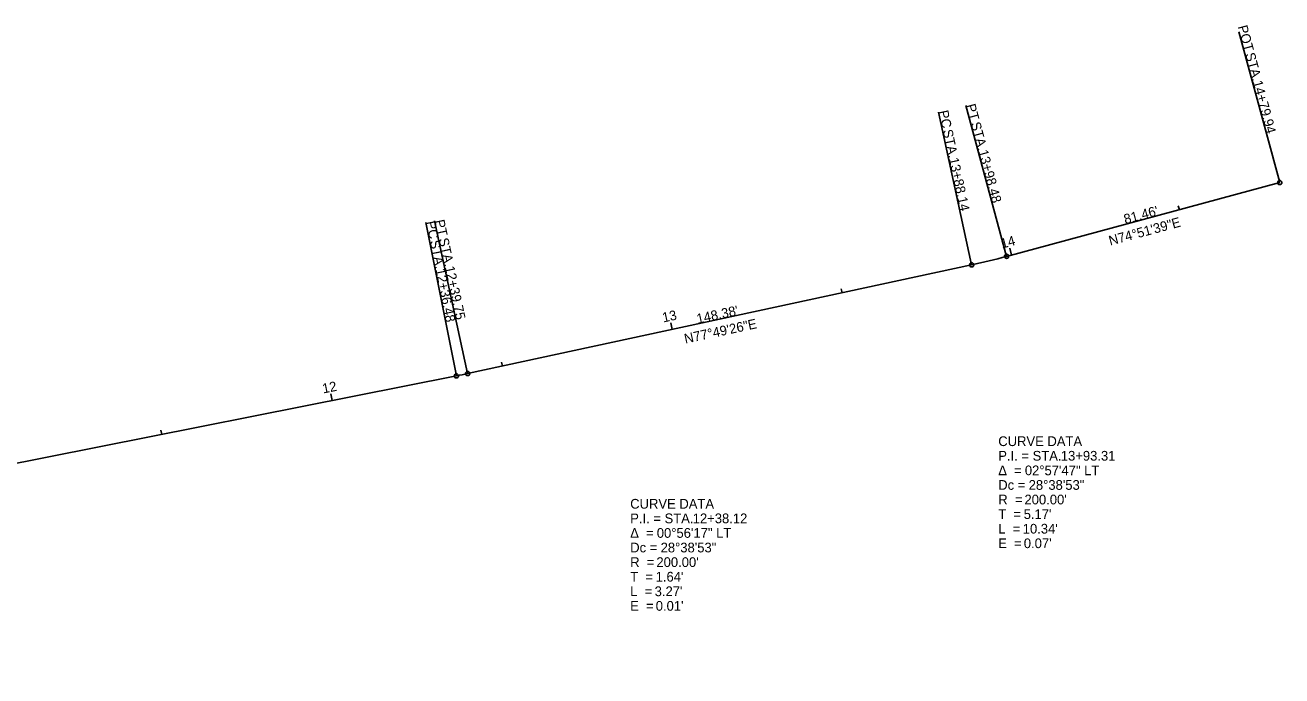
# Model space of a CAD drawing. Extents: x 1749457 to 1750917, y -159140 to -158804.
# Drawn here: x 1750555.2 to 1750916.8, y -158991.8 to -158804.4 of the extents above; entities that cross this region are included whole.
import ezdxf

# ---------------------------------------------------------------- set-up
doc = ezdxf.new("R2010")
doc.units = 0
for name, color, linetype in [('ALIGN', 7, 'Continuous'), ('C-STM STR', 7, 'Continuous'), ('SRF', 7, 'Continuous'), ('SRF-CONT EG MAJ', 7, 'Continuous'), ('SRF-CONT EG MIN', 7, 'Continuous'), ('TEXT', 7, 'Continuous')]:
    doc.layers.add(name, color=color, linetype=linetype)

msp = doc.modelspace()

# ---------------------------------------------------------------- linework, layer by layer
at = {"layer": 'ALIGN'}
for p, q in [((1750837.59, -158871), (1750916.22, -158849.73)), ((1750682.49, -158904.74), (1750827.54, -158873.44)), ((1750244.54, -158991.79), (1750679.29, -158905.4))]:
    msp.add_line(p, q, dxfattribs=at)
for centre, start, end in [((1750785.35, -158677.94), 282.176, 285.1391), ((1750640.31, -158709.24), 281.238, 282.176)]:
    msp.add_arc(centre, 200, start, end, dxfattribs=at)
at = {"layer": 'SRF'}
for p, q in [((1750916.22, -158849.73), (1750904.47, -158806.29)), ((1750827.54, -158873.44), (1750818.05, -158829.46)), ((1750837.59, -158871), (1750825.83, -158827.56)), ((1750679.29, -158905.4), (1750670.52, -158861.27)), ((1750682.49, -158904.74), (1750673, -158860.75))]:
    msp.add_line(p, q, dxfattribs=at)
for centre in [(1750916.22, -158849.73), (1750827.54, -158873.44), (1750837.59, -158871), (1750679.29, -158905.4), (1750682.49, -158904.74)]:
    msp.add_circle(centre, 0.6, dxfattribs=at)
at = {"layer": 'SRF-CONT EG MIN'}
for p, q in [((1750887.32, -158857.55), (1750887.01, -158856.39)), ((1750839.05, -158870.61), (1750838.53, -158868.67)), ((1750790.26, -158881.49), (1750790.01, -158880.31)), ((1750741.38, -158892.03), (1750740.96, -158890.08)), ((1750692.51, -158902.58), (1750692.25, -158901.41)), ((1750643.51, -158912.51), (1750643.12, -158910.55)), ((1750594.46, -158922.26), (1750594.23, -158921.08))]:
    msp.add_line(p, q, dxfattribs=at)

# ---------------------------------------------------------------- texts
at = {"layer": 'C-STM STR'}
for s, rotation, p in [('N74°51\'39"E', 15.1391, (1750867.43, -158867.9)), ('N77°49\'26"E', 12.176, (1750745.16, -158896.13))]:
    msp.add_text(s, height=2.8, rotation=rotation, dxfattribs=at).set_placement(p)
at = {"layer": 'SRF'}
for s, rotation, p in [('POT', 285.1391, (1750904.11, -158804.83)), (' STA. ', 285.1391, (1750905.98, -158811.72)), ('14+79.94', 285.1391, (1750908.41, -158820.72)), ('PC', 282.176, (1750818.03, -158829.22)), ('PT', 285.1391, (1750825.85, -158827.48)), (' STA. ', 285.1391, (1750826.99, -158831.68)), (' STA. ', 282.176, (1750819, -158833.72)), ('13+88.14', 282.176, (1750820.97, -158842.83)), ('13+98.48', 285.1391, (1750829.42, -158840.68)), ('PC', 281.238, (1750670.51, -158861.06)), ('PT', 282.176, (1750673.03, -158860.71)), (' STA. ', 281.238, (1750671.41, -158865.58)), (' STA. ', 282.176, (1750673.95, -158864.96)), ('12+36.48', 281.238, (1750673.23, -158874.72)), ('12+39.75', 282.176, (1750675.91, -158874.08))]:
    msp.add_text(s, height=2.8, rotation=rotation, dxfattribs=at).set_placement(p)
at = {"layer": 'SRF-CONT EG MAJ'}
for s, p in [('CURVE DATA', (1750835.21, -158925.61)), ('P.I. = STA. ', (1750835.21, -158929.81)), ('13+93.31', (1750853.21, -158929.81)), ('Δ  = ', (1750835.21, -158934.01)), ('02°57\'47" LT', (1750842.86, -158934.01)), ('Dc = ', (1750835.21, -158938.21)), ('28°38\'53"', (1750843.96, -158938.21)), ('CURVE DATA', (1750729.29, -158943.63)), ('R  = ', (1750835.21, -158942.41)), ("200.00'", (1750842.75, -158942.41)), ('P.I. = STA. ', (1750729.29, -158947.83)), ('12+38.12', (1750747.28, -158947.83)), ('T  = ', (1750835.21, -158946.61)), ("5.17'", (1750842.53, -158946.61)), ('L  = ', (1750835.21, -158950.81)), ("10.34'", (1750842.25, -158950.81)), ('Δ  = ', (1750729.29, -158952.03)), ('00°56\'17" LT', (1750736.94, -158952.03)), ('E  = ', (1750835.21, -158955.01)), ("0.07'", (1750842.56, -158955.01)), ('Dc = ', (1750729.29, -158956.23)), ('28°38\'53"', (1750738.04, -158956.23)), ('R  = ', (1750729.29, -158960.43)), ("200.00'", (1750736.83, -158960.43)), ('T  = ', (1750729.29, -158964.63)), ("1.64'", (1750736.61, -158964.63)), ('L  = ', (1750729.29, -158968.83)), ("3.27'", (1750736.33, -158968.83)), ('E  = ', (1750729.29, -158973.03)), ("0.01'", (1750736.64, -158973.03))]:
    msp.add_text(s, height=2.8, dxfattribs=at).set_placement(p)
at = {"layer": 'SRF-CONT EG MIN'}
for s, rotation, p in [('14', 15.1391, (1750836.31, -158868.76)), ('13', 12.176, (1750738.82, -158890.03)), ('12', 11.238, (1750640.96, -158910.47))]:
    msp.add_text(s, height=2.8, rotation=rotation, dxfattribs=at).set_placement(p)
at = {"layer": 'TEXT'}
for s, rotation, p in [("81.46'", 15.1391, (1750871.76, -158861.72)), ("148.38'", 12.176, (1750748.71, -158890.41))]:
    msp.add_text(s, height=2.8, rotation=rotation, dxfattribs=at).set_placement(p)

doc.saveas('drawing.dxf')
